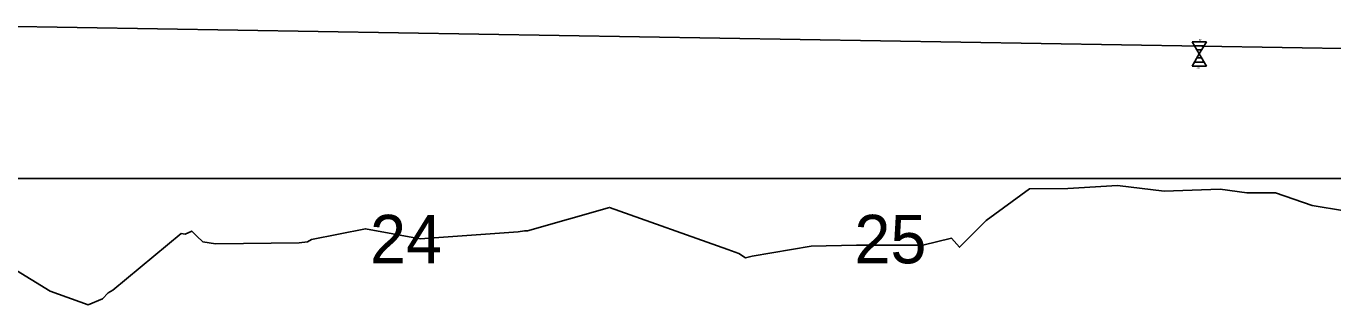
# Model space of a CAD drawing. Extents: x 573468 to 580768, y -57414 to -51768.
# Drawn here: x 575091.5 to 575361.5, y -53717.3 to -53659.8 of the extents above; entities that cross this region are included whole.
import ezdxf

# ---------------------------------------------------------------- set-up
doc = ezdxf.new("R2010")
doc.units = 0
for name, color, linetype in [('Exist Profile Cell', 7, 'Continuous'), ('Exist Vertical Profile Ground Line', 7, 'Continuous'), ('Exist Vertical Profile Horizontal Axis Label Major', 7, 'Continuous'), ('Pattern 2', 7, 'Continuous'), ('Prop Vertical Profile Grade', 7, 'Continuous')]:
    doc.layers.add(name, color=color, linetype=linetype)

msp = doc.modelspace()

# ---------------------------------------------------------------- linework, layer by layer
at = {"layer": 'Exist Profile Cell'}
msp.add_line((573531.99, -53691.24), (576075.95, -53691.24), dxfattribs=at)
at = {"layer": 'Exist Vertical Profile Ground Line'}
for points in [[(575088.61, -53709.64), (575096.46, -53714.47), (575104.34, -53717.3), (575107.29, -53716.08), (575108.48, -53714.8), (575109.46, -53714.29), (575123.56, -53702.62), (575124.36, -53702.72), (575125.73, -53702.09), (575126.8, -53703.12), (575128.05, -53704.33), (575130.68, -53704.7), (575147.91, -53704.53), (575149.67, -53704.3), (575150.49, -53703.85), (575161.64, -53701.61), (575172.91, -53703.66), (575193.18, -53702.24), (575194.52, -53702.07), (575195.12, -53702.04), (575212.08, -53697.2), (575236.54, -53705.92), (575238.81, -53706.74), (575240.19, -53707.59), (575241.54, -53707.29), (575253.76, -53705.17), (575263.13, -53704.97), (575276.79, -53704.98), (575282.74, -53703.55), (575284.42, -53705.42), (575289.9, -53699.88), (575298.89, -53693.4), (575306.81, -53693.27), (575317.04, -53692.7), (575326.67, -53693.86)], [(575326.67, -53693.86), (575338.25, -53693.41), (575343.75, -53694.18), (575349.71, -53694.2), (575357.29, -53696.81), (575370.61, -53699.02)]]:
    msp.add_lwpolyline(points, dxfattribs=at)
at = {"layer": 'Pattern 2'}
for p, q in [((575332.47, -53663.04), (575335.4, -53663.04)), ((575332.47, -53663.04), (575333.94, -53665.54)), ((575333.94, -53665.54), (575335.4, -53663.04)), ((575332.47, -53668.04), (575333.94, -53665.54)), ((575332.96, -53663.88), (575334.91, -53663.88)), ((575333.45, -53664.71), (575334.43, -53664.71)), ((575333.94, -53665.54), (575335.4, -53668.04)), ((575332.47, -53668.04), (575335.4, -53668.04)), ((575332.96, -53667.21), (575334.91, -53667.21)), ((575333.45, -53666.38), (575334.43, -53666.38))]:
    msp.add_line(p, q, dxfattribs=at)
at = {"layer": 'Prop Vertical Profile Grade'}
msp.add_line((575083.94, -53659.82), (575375.13, -53664.65), dxfattribs=at)

# ---------------------------------------------------------------- texts
at = {"layer": 'Exist Vertical Profile Horizontal Axis Label Major'}
for s, p in [('24', (575162.58, -53708.74)), ('25', (575262.68, -53708.74))]:
    msp.add_text(s, height=10, dxfattribs=at).set_placement(p)
at = {"layer": 'Pattern 2'}
for s, p in [('6"', (575333.82, -53662.94)), ('-6"', (575333.36, -53668.65))]:
    msp.add_text(s, height=0.5, rotation=360, dxfattribs=at).set_placement(p)

doc.saveas('drawing.dxf')
